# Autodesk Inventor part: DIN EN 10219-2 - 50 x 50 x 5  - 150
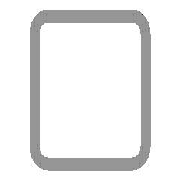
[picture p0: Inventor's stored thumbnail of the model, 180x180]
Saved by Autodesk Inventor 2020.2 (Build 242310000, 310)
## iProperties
_CCFamilyMember: 16
_CCFamilyDisplayName: DIN EN 10219-2 (Quadratisches Hohlprofil - Kaltgeformt) - Kaltgeformte, geschweißte Baustahl-Hohlprofile aus unlegiertem Feinkorn-Baustahl
_FrameMemberDoc: Frame Member File
_Version: 15.0.0
_GetPNFromCC: 1
IsCustomPart: 1
Created: 2019-01
Part Number: DIN EN 10219-2 - 50 x 50 x 5  - 150
Material: Stahl, weich
Description: Kaltgeformte, geschweißte Baustahl-Hohlprofile aus unlegiertem Feinkorn-Baustahl
Document SubType Name: Modeling
Standard: DIN
Designer: lutzd
Standard Revision: 2006-07
Standards Organization: DIN
Language: de-DE
Size Designation: 50 x 50 x 5
Categories: <MemberInstance><Categories><Category DisplayName="Profile" InternalName="089c4875-fa83-4c05-b084-43b9cc11f5ed" Mnemonic="GRDR"><CategoryParameter DisplayName="
Stock Number: 50 x 50 x 5
Mass: 979.856 g
Surface Area: 519.134 cm^2
Volume: 124.822 cm^3
Density: 7.85 g/cm^3
Appearance: Semi-Polished(8)
G_L: 150,000 mm
G_W: 50,000 mm
G_H: 50,000 mm
Mass: 0,98 kg
VLT_Material: Stahl, weich
+D70146FB-17BB-4B2C-8B84-7632EEB53775+SCHNITTDETAIL1: Schnittwinkel 90,00 grd
DocNumber: ADSK-014417
Folder: .
Dimensions: 50x50x150 mm
Title: Profil-Bauteil
Author: lutzd
Revision Number: -
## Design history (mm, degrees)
node "Startebene"
node "Endebene"
sketch "Skizze"
  geometry: L1 (-25, -15)-(-25, 15); L2 (-15, 25)-(15, 25); L3 (25, 15)-(25, -15); L4 (15, -25)-(-15, -25); L5 (-15, 20)-(15, 20); L6 (20, 15)-(20, -15); L7 (15, -20)-(-15, -20); L8 (-20, -15)-(-20, 15); L9 (0, 37.899)-(0, -37.899) reference; L10 (-37.899, 0)-(37.899, 0) reference; A1 r 10 centre (-15, -15) between (-25, -15) and (-15, -25); A2 r 10 centre (-15, 15) between (-15, 25) and (-25, 15); A3 r 10 centre (15, 15) between (25, 15) and (15, 25); A4 r 10 centre (15, -15) between (15, -25) and (25, -15); A5 r 5 centre (-15, 15) between (-15, 20) and (-20, 15); A6 r 5 centre (15, 15) between (20, 15) and (15, 20); A7 r 5 centre (15, -15) between (15, -20) and (20, -15); A8 r 5 centre (-15, -15) between (-20, -15) and (-15, -20)
  constraints: 16 end point, 16 point on circle, 8 centre point, 8 tangent, 4 parallel, 3 equal radius, 2 perpendicular, 7 other
  dimensions: "d7" = 10 radius of A1 (= G_IR); "d10" = 50 distance between parallel lines of L2 L4 (= G_H); "d11" = 50 distance between parallel lines of L1 L3 (= G_W); "d12" = 5 distance between parallel lines of L3 L6 (= G_T); "d15" = 25 distance between parallel lines of L2 L10 (= 0.5 x d10); "d16" = 25 distance between parallel lines of L9 L3 (= 0.5 x d11)
extrude "Körper" new body sketch "Skizze" stored distance "d3" = 150 (= G_L); taper "d4" = 0 deg
node "Driven Length"
  sketch "Sketch3"
    geometry: L1 (0, 0)-(10, 0) reference
    constraints: 2 end point, 1 horizontal
  workplane "Work Plane3"
  sketch "Sketch4"
    geometry: L1 (-2, 50)-(12, 50) reference; L2 (-2, 200)-(12, 200) reference
    dimensions: "d18" = 150 distance between parallel lines of L1 L2 (derived)
workplane "Arbeitsebene4"
feature "Trennen1"
sketch "Skizze5"
  geometry: L1 (30, 150)-(0, 150) reference; L2 (15, 150)-(15, 31); 4 further points
  constraints: 2 end point, 2 point on line, 1 coincident, 1 midpoint, 1 vertical
  dimensions: "d19" = 62 distance of point (15, 69) point (15, 131); "d20" = 19 distance from line of L1 point (15, 131); "d21" = 38 distance of point (15, 31) point (15, 69)
hole "Bohrung1" sketch "Skizze5" at (15, 31), (15, 69), (15, 131) diameter "d22" = 6.647; stored, may be unused: countersink angle "d26" = 90 deg, drill point angle "d28" = 118 deg; dims "d23" = 16, "d24" = 4, "d25" = 2, "d27" = 8
body "Solid1"
other parameters: "G_W" = 50 [user parameter; used in 1 equation term], "G_H" = 50 [user parameter; used in 1 equation term], "G_T" = 5 [user parameter; used in 1 equation term], "G_IR" = 10 [user parameter; used in 1 equation term], "G_L" = 150 (= d18) [user parameter; used in 1 equation term], "G_OFFSET_END" = 0 [user parameter; used in 1 equation term], "d17" = 90 deg
